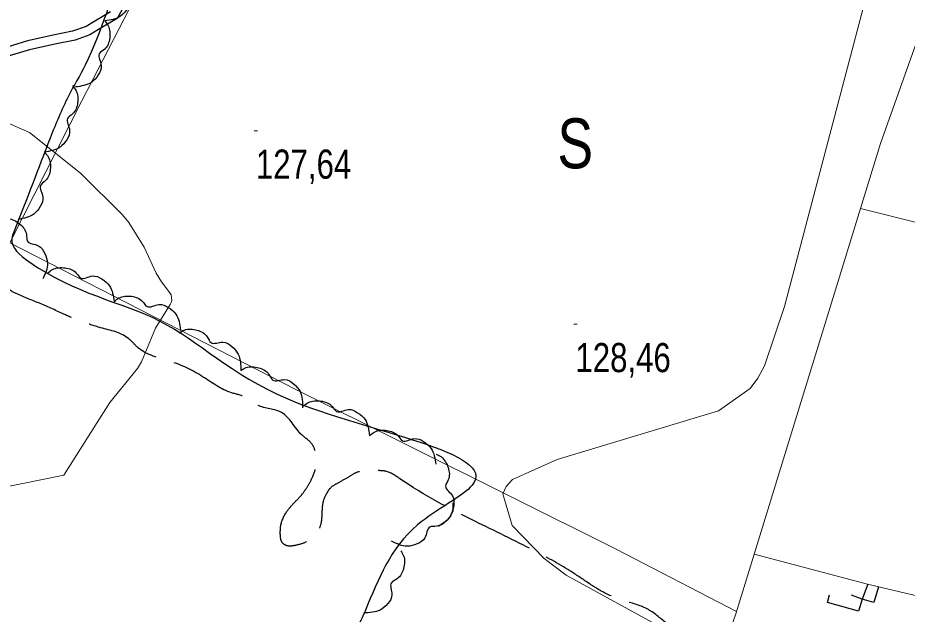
# Model space of a CAD drawing. Extents: x 483843 to 488449, y 4381269 to 4384483.
# Drawn here: x 486216 to 486483.2, y 4383267.7 to 4383446.8 of the extents above; entities that cross this region are included whole.
import ezdxf
from ezdxf.enums import TextEntityAlignment as Align

# ---------------------------------------------------------------- set-up
doc = ezdxf.new("R2010")
doc.units = 0
doc.header["$LTSCALE"] = 3.8
doc.linetypes.add('LONG_DASHED', pattern=[7.5, 6, -1.5])
doc.linetypes.add('MEDIUM_DASHED', pattern=[4.5, 3, -1.5])
for name, color, linetype, lineweight in [('15', 7, 'LONG_DASHED', 13), ('27', 7, 'Continuous', 25), ('38', 7, 'Continuous', 25), ('48', 7, 'MEDIUM_DASHED', 25), ('51', 7, 'Continuous', 13), ('7', 7, 'Continuous', 13), ('9', 7, 'Continuous', 13)]:
    doc.layers.add(name, color=color, linetype=linetype, lineweight=lineweight)
doc.layers.add('31', color=7, linetype='Continuous')

msp = doc.modelspace()

# ---------------------------------------------------------------- linework, layer by layer
at = {"layer": '15'}
msp.add_spline([(485400.79, 4383245.56), (485406.29, 4383244.41), (485437.45, 4383238.77), (485468.96, 4383231.4), (485504.33, 4383230.87), (485548.91, 4383220.24), (485591.04, 4383211.58), (485622.86, 4383204.36), (485651.32, 4383198.17), (485680.8, 4383195.25), (485706.08, 4383191.57), (485722.37, 4383193.95), (485735.23, 4383201.55), (485745.53, 4383213.76), (485759.02, 4383234.02), (485775.19, 4383262.78), (485795.18, 4383296.65), (485816.27, 4383323.61), (485841.16, 4383349.54), (485867.84, 4383369.45), (485913.47, 4383388.85), (485935.22, 4383394.97), (485958.89, 4383388.99), (485973.47, 4383381.81), (485979.32, 4383377.07), (485984.47, 4383370.85), (485987.04, 4383362.27), (485987.36, 4383354.02), (485987.36, 4383343.75), (485982.84, 4383337.15), (485969.6, 4383328.73), (485958.55, 4383321.85), (485945.63, 4383309.53), (485931.32, 4383300.15), (485906.76, 4383286.36), (485891.85, 4383276.39), (485880.57, 4383264.12), (485871.36, 4383244.47), (485865.12, 4383222.84), (485860.75, 4383191.43), (485865.12, 4383163.11), (485877.56, 4383143.14), (485893.96, 4383132.18), (485911.26, 4383131.69), (485923.31, 4383135.71), (485933.99, 4383143.04), (485949.29, 4383153.83), (485962.9, 4383167.19), (485985.6, 4383171.87), (486005.81, 4383170.22), (486029.34, 4383160.05), (486043.95, 4383149.41), (486042.89, 4383138.86), (486041.88, 4383131.75), (486041.4, 4383119.4), (486046.63, 4383078.7), (486048.42, 4383062.79), (486056.08, 4383044.24), (486065.61, 4383030.31), (486078.82, 4383011.67), (486095.82, 4382995.68), (486117.1, 4382985.39), (486141.45, 4382970.26), (486161.85, 4382961.49), (486185.85, 4382957.83), (486221.05, 4382956.33), (486256.43, 4382956.62), (486292.45, 4382960.13), (486324.15, 4382965.13)], degree=3, dxfattribs=at)
at = {"layer": '27'}
for points in [[(486610.86, 4384044.96), (486626.92, 4384050.28), (486637.16, 4384047.74), (486652.05, 4384044.37), (486668.53, 4384042.49), (486656.8, 4383988.7), (486633.28, 4383928.86), (486626.29, 4383912.38), (486620.95, 4383890.47), (486618.98, 4383873.39), (486617.47, 4383861.93), (486622.54, 4383859.83), (486631.45, 4383858.8), (486644.63, 4383856.29), (486649.12, 4383845.49), (486645.98, 4383835.48), (486644.53, 4383823.42), (486643.59, 4383804.83), (486644.04, 4383789.06), (486650.17, 4383776.97), (486661.43, 4383767.05), (486666.65, 4383759.32), (486665.61, 4383749.81), (486664.24, 4383748.18), (486659.87, 4383747.12), (486650.35, 4383747.78), (486629.58, 4383749.13), (486612.5, 4383751.02), (486592.66, 4383759.56), (486583.46, 4383745.88), (486580.74, 4383723.11), (486572.16, 4383689.84), (486560.68, 4383659.02), (486553.32, 4383631.81), (486543.18, 4383605.32), (486532.56, 4383576.21), (486523.53, 4383553.45), (486518.77, 4383540.54), (486501.4, 4383543.49), (486476.15, 4383556.3), (486468.29, 4383557.62), (486465.07, 4383557.96), (486462.29, 4383558.08), (486460.26, 4383557.81), (486439.29, 4383544.45), (486415.17, 4383526.49), (486391.53, 4383510.54), (486385.69, 4383506.57), (486377.62, 4383503.39), (486371.16, 4383503.41), (486344.21, 4383501.99), (486329.53, 4383482.99), (486328.89, 4383480.37), (486326.87, 4383475.75), (486312.85, 4383471.45), (486300.33, 4383482.51), (486290.76, 4383490.08), (486283.31, 4383493.56), (486272.61, 4383495.89), (486284, 4383520.94), (486252.05, 4383537.68), (486229.62, 4383543.55), (486216.83, 4383551.46), (486203.95, 4383558.48), (486174.8, 4383524.83), (486205.26, 4383519.21), (486220.9, 4383511.34), (486230.24, 4383508.13), (486241.13, 4383503.92), (486264.65, 4383495.7), (486250.48, 4383465.06), (486236.28, 4383432.55), (486231.27, 4383423.25), (486225.77, 4383410.64), (486214.94, 4383382.73), (486214.23, 4383380.42), (486219.38, 4383373.59), (486258.75, 4383355.69), (486297.13, 4383332.33), (486352.51, 4383306.4), (486336.13, 4383294.48), (486320.46, 4383268.89), (486317.3, 4383262.94), (486310.85, 4383257.93), (486295.11, 4383254.25), (486285.76, 4383251.31), (486282.23, 4383245.35), (486279.78, 4383236.83), (486280.35, 4383218.97), (486309.23, 4383192.29), (486315, 4383181.33)], [(486250.78, 4383465.75), (486251.83, 4383464.32), (486252.31, 4383460.56), (486250.75, 4383457.21), (486249.21, 4383455.85), (486249.85, 4383452.35), (486248.94, 4383449.51), (486246.91, 4383447.27), (486242.16, 4383445.84)], [(486242.15, 4383445.84), (486243.18, 4383444.4), (486243.64, 4383440.64), (486242.05, 4383437.3), (486240.5, 4383435.95), (486241.11, 4383432.45), (486240.19, 4383429.61), (486238.13, 4383427.39), (486233.38, 4383426)], [(486232.43, 4383426.45), (486233.49, 4383425.02), (486234.01, 4383421.26), (486232.48, 4383417.91), (486230.96, 4383416.53), (486231.62, 4383413.04), (486230.74, 4383410.18), (486228.73, 4383407.93), (486223.99, 4383406.45)], [(486224.1, 4383406.41), (486225.19, 4383405.01), (486225.8, 4383401.27), (486224.35, 4383397.87), (486222.85, 4383396.46), (486223.6, 4383392.99), (486222.79, 4383390.11), (486220.83, 4383387.81), (486216.13, 4383386.23)], [(486211.44, 4383386.34), (486213.22, 4383386.46), (486216.65, 4383384.84), (486218.63, 4383381.72), (486218.95, 4383379.69), (486222.24, 4383378.34), (486224.14, 4383376.04), (486224.94, 4383373.13), (486223.59, 4383368.35)], [(486225.05, 4383370.13), (486226.48, 4383371.18), (486230.24, 4383371.68), (486233.59, 4383370.12), (486234.96, 4383368.59), (486238.45, 4383369.24), (486241.3, 4383368.34), (486243.55, 4383366.32), (486244.99, 4383361.57)], [(486245, 4383361.58), (486246.43, 4383362.63), (486250.19, 4383363.13), (486253.54, 4383361.58), (486254.9, 4383360.05), (486258.4, 4383360.69), (486261.25, 4383359.8), (486263.49, 4383357.77), (486264.94, 4383353.03)], [(486264.5, 4383352.17), (486266.06, 4383353.01), (486269.86, 4383352.96), (486272.95, 4383350.94), (486274.08, 4383349.22), (486277.63, 4383349.36), (486280.32, 4383348.06), (486282.25, 4383345.73), (486283, 4383340.83)], [(486283.02, 4383340.87), (486284.58, 4383341.71), (486288.38, 4383341.68), (486291.48, 4383339.68), (486292.62, 4383337.97), (486296.17, 4383338.12), (486298.87, 4383336.84), (486300.81, 4383334.52), (486301.58, 4383329.62)], [(486301.89, 4383330.21), (486303.33, 4383331.24), (486307.1, 4383331.68), (486310.43, 4383330.08), (486311.77, 4383328.52), (486315.28, 4383329.12), (486318.11, 4383328.18), (486320.32, 4383326.12), (486321.7, 4383321.36)], [(486321.68, 4383321.3), (486323.11, 4383322.35), (486326.87, 4383322.84), (486330.21, 4383321.29), (486331.58, 4383319.75), (486335.08, 4383320.39), (486337.92, 4383319.5), (486340.16, 4383317.47), (486341.61, 4383312.72)], [(486341.69, 4383315.72), (486343.25, 4383314.88), (486345.3, 4383311.68), (486345.31, 4383307.99), (486344.5, 4383306.11), (486346.57, 4383303.21), (486346.97, 4383300.25), (486346.09, 4383297.36), (486342.4, 4383294.04)], [(486346.66, 4383301.1), (486346.72, 4383299.32), (486344.99, 4383295.95), (486341.8, 4383294.08), (486339.77, 4383293.82), (486338.31, 4383290.58), (486335.95, 4383288.75), (486333.01, 4383288.06), (486328.28, 4383289.56)], [(486331.04, 4383286.74), (486331.9, 4383285.19), (486331.9, 4383281.39), (486329.93, 4383278.27), (486328.23, 4383277.12), (486328.42, 4383273.57), (486327.16, 4383270.86), (486324.86, 4383268.9), (486319.97, 4383268.08)]]:
    msp.add_spline(points, degree=3, dxfattribs=at)
at = {"layer": '38', "linetype": 'MEDIUM_DASHED'}
for points in [[(486249.47, 4383453.09), (486245.9, 4383446.58), (486240.31, 4383443.23), (486237.72, 4383441.66), (486233.26, 4383440.11), (486227.21, 4383438.83), (486219.54, 4383437.14)], [(486218.95, 4383439.84), (486199.85, 4383433.93), (486178.84, 4383422.97), (486173.35, 4383417.64), (486169.06, 4383414.62), (486162.57, 4383413.67), (486155.9, 4383413.77), (486144.31, 4383415.33), (486137.01, 4383417.05), (486130.1, 4383419.64), (486123.76, 4383422.88), (486118.37, 4383426.26), (486110.11, 4383428.91)]]:
    msp.add_lwpolyline(points, dxfattribs=at)
at = {"layer": '38'}
for points in [[(486243.84, 4383448.57), (486238.88, 4383445.6), (486236.53, 4383444.17), (486232.52, 4383442.78), (486226.62, 4383441.53), (486218.95, 4383439.84)], [(486219.54, 4383437.14), (486200.84, 4383431.66), (486180.29, 4383420.95), (486174.92, 4383415.74), (486170, 4383412.27), (486166.77, 4383411.8)]]:
    msp.add_lwpolyline(points, dxfattribs=at)
at = {"layer": '38', "linetype": 'LONG_DASHED'}
for points in [[(486294.89, 4383291.47), (486295.01, 4383294.17), (486296.95, 4383298.64), (486299.24, 4383301.31), (486300.99, 4383303.16), (486302.83, 4383305.69), (486304.37, 4383308.44), (486305.22, 4383310.61), (486305.45, 4383316.08), (486304.58, 4383318.49), (486301.4, 4383321.47), (486295.27, 4383328.23), (486288.1, 4383330.44), (486284.68, 4383332.74), (486280.27, 4383334.15), (486271.56, 4383339), (486261.72, 4383343.65), (486252.25, 4383347.61), (486249.44, 4383350.35), (486240.93, 4383353.7), (486234.96, 4383355.66), (486230.11, 4383357.68), (486222.8, 4383360.94), (486215.57, 4383363.97), (486205.46, 4383371.01), (486199.98, 4383376.04), (486189.49, 4383381.82), (486185.65, 4383386.68), (486183.73, 4383388.73), (486177.58, 4383394.07), (486173.62, 4383394.96), (486168.45, 4383395.71), (486164.03, 4383395.99), (486161.91, 4383394.9), (486159.71, 4383393.06), (486157.49, 4383390.01), (486156.18, 4383387.78), (486154.89, 4383386.67), (486152.89, 4383388.5)], [(486317.24, 4383185.8), (486319.04, 4383180.52), (486320.72, 4383177.34), (486321.79, 4383173.73), (486323.09, 4383169.88), (486324.3, 4383165.06), (486324.47, 4383161.46), (486324.29, 4383159.28), (486323.9, 4383158.39), (486322.93, 4383153.68), (486321.42, 4383152.57), (486318.98, 4383149.98), (486316.78, 4383148.59), (486310.97, 4383146.49), (486306.3, 4383144.84), (486304.34, 4383144.04), (486300.49, 4383142.67), (486298.14, 4383141.2), (486296.76, 4383139.27), (486294.9, 4383134.87), (486294.19, 4383132.1), (486293.47, 4383129.19), (486292.8, 4383124.54), (486293.08, 4383123.34), (486297.42, 4383122.38), (486304.49, 4383123.55), (486306.77, 4383125.54), (486306.91, 4383129.59), (486307.44, 4383135.14), (486308.68, 4383138.42), (486310.28, 4383139.83), (486314.81, 4383141.94), (486322.62, 4383147.23), (486325.88, 4383149.58), (486329.35, 4383151.26), (486332, 4383153.02), (486333.97, 4383153.97), (486339.41, 4383156.52), (486348.85, 4383160.96), (486352.73, 4383164.36), (486358.34, 4383168.4), (486363.77, 4383170.58), (486366.43, 4383172.79), (486369.38, 4383174.7), (486375.86, 4383176.78), (486379.94, 4383178.15), (486385.05, 4383179.05), (486387.46, 4383179.77), (486390.04, 4383181.6), (486391.35, 4383184.21), (486392.14, 4383186.45), (486393.02, 4383190.19), (486393.97, 4383193.93), (486397.4, 4383197.56), (486399.4, 4383201.2), (486402.12, 4383212.8), (486407.47, 4383230.2), (486411.35, 4383234.2), (486415.33, 4383239.32), (486416.45, 4383244.41), (486416.93, 4383251.68), (486416.98, 4383254.75), (486414.95, 4383259.96), (486414, 4383261.85), (486410.82, 4383264.97), (486405.03, 4383269.26), (486397.94, 4383271.76), (486391.52, 4383274.48), (486387.43, 4383277.01), (486381.86, 4383280.69), (486371.06, 4383286.78), (486353.33, 4383295.59), (486330.78, 4383308.36), (486326.53, 4383310.6), (486323.91, 4383310.79), (486320.83, 4383310.83), (486317.6, 4383310.13), (486315.02, 4383308.66), (486311.92, 4383306.91), (486309.8, 4383305.44), (486308.8, 4383303.95), (486307.79, 4383301.64), (486307.47, 4383299.84), (486307.18, 4383295.5), (486306.4, 4383293.03), (486305.4, 4383291.69), (486302.67, 4383289.41), (486299.42, 4383288.33), (486296.72, 4383288.29), (486295.39, 4383289.29), (486294.89, 4383291.47)]]:
    msp.add_spline(points, degree=3, dxfattribs=at)
at = {"layer": '48'}
for points in [[(486471.29, 4383276.64), (486469.61, 4383272.22), (486466.47, 4383273.39)], [(486474.49, 4383275.89), (486473.11, 4383271.21), (486469.61, 4383272.22), (486468.54, 4383268.53), (486459.21, 4383271.2), (486459.85, 4383273.46)]]:
    msp.add_lwpolyline(points, dxfattribs=at)
at = {"layer": '51'}
msp.add_line((486235.23, 4383421.84), (486274.67, 4383498.26), dxfattribs=at)
for points in [[(486475.09, 4383409.02), (486501.13, 4383482.33), (486547.72, 4383628.44), (486566.43, 4383688.35), (486608.69, 4383835.57), (486625.06, 4383888.83), (486646.53, 4383962.89), (486662.22, 4384021.19), (486667.98, 4384045.79), (486675.93, 4384077.57), (486678.67, 4384105.97), (486682.95, 4384117.09), (486685.73, 4384122), (486688.32, 4384125.34), (486692.13, 4384129.19), (486692.86, 4384130)], [(486431.91, 4383268.44), (486395.53, 4383287.25), (486299.79, 4383335.07), (486213.61, 4383379.15), (486235.23, 4383421.84)], [(486358.48, 4383052.84), (486378.35, 4383098.78), (486393.58, 4383151.09), (486408.09, 4383200.41), (486431.72, 4383267.82), (486475.09, 4383409.02)], [(486469.1, 4383389.53), (486577.07, 4383362.46), (486555.98, 4383330.28), (486547.09, 4383317.42), (486545.53, 4383313.32), (486544.48, 4383308.6), (486540.51, 4383303.14)], [(486437.22, 4383285.73), (486471.24, 4383276.64), (486506.32, 4383268.41), (486518.14, 4383276.57), (486520.19, 4383273.09), (486521.69, 4383272.91), (486523.65, 4383273.79), (486526.09, 4383276.75), (486526.75, 4383280.72), (486528.26, 4383286.33), (486530.33, 4383289.17)]]:
    msp.add_lwpolyline(points, dxfattribs=at)
at = {"layer": '7'}
for p, q in [((486287.05, 4383412.83), (486288.05, 4383412.83)), ((486383.02, 4383354.73), (486384.02, 4383354.73))]:
    msp.add_line(p, q, dxfattribs=at)
at = {"layer": '9'}
for points in [[(486485.51, 4383509.07), (486446.28, 4383360.11), (486440.31, 4383342.26), (486438.25, 4383338.59), (486436.01, 4383335.46), (486426.45, 4383328.75), (486377.99, 4383314.15), (486364.59, 4383308.09), (486362.73, 4383306.03), (486361.67, 4383303.79), (486364.53, 4383294.3), (486374.11, 4383284.36), (486380.7, 4383279.42), (486408.65, 4383264.11)], [(486178.49, 4383298.99), (486229.86, 4383309.38), (486243.7, 4383331.23), (486252.01, 4383341.49), (486253.21, 4383343.5), (486257.41, 4383353.55), (486261.84, 4383360.64), (486262.09, 4383361.27), (486262.26, 4383361.86), (486262.07, 4383363.57), (486261.15, 4383365.02), (486259.25, 4383367.46), (486257.58, 4383370.06), (486253.97, 4383377.9), (486249.37, 4383385.28), (486247.44, 4383387.62), (486234.83, 4383400.1), (486219.57, 4383412.31), (486172.75, 4383432.81)]]:
    msp.add_lwpolyline(points, dxfattribs=at)

# ---------------------------------------------------------------- texts
at = {"layer": '31', "width": 0.8}
msp.add_text('S', height=15, dxfattribs=at).set_placement((486383.47, 4383401.58), align=Align.CENTER)
at = {"layer": '7', "width": 0.8}
for s, p in [('127,64', (486287.55, 4383398.46)), ('128,46', (486383.52, 4383340.36))]:
    msp.add_text(s, height=8.75, dxfattribs=at).set_placement(p)

doc.saveas('drawing.dxf')
